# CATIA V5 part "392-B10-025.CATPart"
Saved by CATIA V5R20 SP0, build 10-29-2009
Part number: 392-B10-025
Definition: NONE
Nomenclature: 392-B10-025
Source: Unknown
Description: 392-B10-025
Bounding box of the stored display mesh (mm): x 0 to 25, y -4.695 to 4.695, z -4.65 to 4.65
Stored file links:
  C:\Users\Utente\Desktop\IO LAVORO\3D X SITO CF\X SITO\3D files 392B\392-B10-025.CATPart
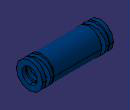
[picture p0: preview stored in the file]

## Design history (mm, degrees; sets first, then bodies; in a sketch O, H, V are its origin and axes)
Body1 "392-B10-025" (main body)
  Solid1: solid without history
